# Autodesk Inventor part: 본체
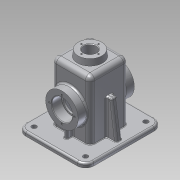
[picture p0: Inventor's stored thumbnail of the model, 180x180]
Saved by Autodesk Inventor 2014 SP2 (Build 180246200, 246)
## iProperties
Created: 2016-08
Part Number: 본체
Material: 알루미늄 6061
Document SubType Name: Modeling
Designer: user
Density: 2.71 g/cm^3
Appearance: 알루미늄 - 평지
Mass: 799.652 g
Surface Area: 913.3 cm^2
Volume: 295.075 cm^3
Author: user
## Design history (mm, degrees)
sketch "스케치2"
  geometry: L1 (52.5, -60)-(-52.5, -60); L2 (-52.5, -60)-(-52.5, 60); L3 (-52.5, 60)-(52.5, 60); L4 (52.5, 60)-(52.5, -60); L5 (52.5, -60)-(-52.5, 60); L6 (-52.5, -60)-(52.5, 60); 1 further point
  constraints: 12 end point, 2 midpoint, 2 parallel, 1 horizontal, 1 perpendicular
  dimensions: "d0" = 105 distance of L2.end L3.end; "d1" = 120 distance of L1.end L2.end
extrude "돌출1" new body sketch "스케치2" distance "d2" = 3; taper "d3" = 0 deg
sketch "스케치3"
  geometry: L1 (57.5, -65)-(-57.5, -65); L2 (-57.5, -65)-(-57.5, 65); L3 (-57.5, 65)-(57.5, 65); L4 (57.5, 65)-(57.5, -65); L5 (57.5, -65)-(-57.5, 65); L6 (-57.5, -65)-(57.5, 65); 1 further point
  constraints: 12 end point, 2 midpoint, 2 parallel, 1 horizontal, 1 perpendicular
  dimensions: "d4" = 115 distance of L2.end L3.end; "d5" = 130 distance of L1.end L2.end
extrude "돌출2" join sketch "스케치3" distance "d6" = 7; taper "d7" = 0 deg
sketch "스케치4"
  geometry: L1 (-32.5, -32.5)-(32.5, -32.5); L2 (32.5, -32.5)-(32.5, 32.5); L3 (32.5, 32.5)-(-32.5, 32.5); L4 (-32.5, 32.5)-(-32.5, -32.5); L5 (-32.5, -32.5)-(32.5, 32.5); L6 (32.5, -32.5)-(-32.5, 32.5); 1 further point
  constraints: 12 end point, 2 midpoint, 2 parallel, 1 horizontal, 1 perpendicular
  dimensions: "d8" = 65 distance of L3.end L2.end; "d9" = 65 distance of L2.end L1.end
extrude "돌출3" join sketch "스케치4" distance "d10" = 100; taper "d11" = 0 deg
sketch "스케치5"
  geometry: L1 (32.5, -32.5)-(-32.5, -32.5) reference; L2 (-32.5, -32.5)-(-32.5, 32.5) reference; L3 (-32.5, 32.5)-(32.5, 32.5) reference; L4 (32.5, 32.5)-(32.5, -32.5) reference; L5 (27.5, 27.5)-(-27.5, 27.5); L6 (-27.5, 27.5)-(-27.5, -27.5); L7 (-27.5, -27.5)-(27.5, -27.5); L8 (27.5, -27.5)-(27.5, 27.5); 1 further point
  constraints: 8 end point, 3 other
  dimensions: "d12" = 5 distance between parallel lines of L3 L5
extrude "돌출4" cut sketch "스케치5" distance "d13" = 105; taper "d14" = 0 deg
sketch "스케치6"
  geometry: C1 r 27.5 at (32.5, 45); 1 further point
  constraints: 1 centre point, 1 vertical alignment
  dimensions: "d15" = 55 diameter of C1; "d16" = 55 distance of point (32.5, -10) C1.centre
extrude "돌출5" join sketch "스케치6" distance "d17" = 15; taper "d18" = 0 deg
fillet "모깎기1" dims "d19" = 8
fillet "모깎기2" dims "d20" = 8
fillet "모깎기3" dims "d21" = 3
sketch "스케치9"
  geometry: L1 (-57.5, -65)-(-57.5, 65) reference; L2 (-32.5, 24.5)-(-32.5, -24.5) reference; L3 (-49.5, 5)-(-49.5, -5); L4 (-49.5, -5)-(-32.5, -5); L5 (-49.5, 5)-(-32.5, 5); L6 (-32.5, 5)-(-32.5, -5); 2 further points
  constraints: 8 end point, 2 perpendicular, 2 point on line, 1 collinear, 1 horizontal alignment, 1 midpoint, 1 parallel
  dimensions: "d36" = 10 distance of L3.start L3.end; "d37" = 8 distance between parallel lines of L1 L3
extrude "돌출7" join sketch "스케치9" distance "d38" = 60; taper "d39" = 0 deg
feature "면 기울기1" dims angle "d40" = 8 deg
sketch "스케치10"
  geometry: L1 (24.5, -32.5)-(-24.5, -32.5) reference; L2 (-3, -42.5)-(3, -42.5); L3 (-24.5, -27.5)-(24.5, -27.5) reference; L4 (3, -42.5)-(3, -27.5); L5 (-3, -42.5)-(-3, -27.5); L6 (-3, -27.5)-(3, -27.5); 2 further points
  constraints: 8 end point, 2 perpendicular, 2 point on line, 1 collinear, 1 midpoint, 1 parallel, 1 vertical alignment
  dimensions: "d41" = 15 distance of L2.end L4.end; "d42" = 6 distance of L2.start L2.end
extrude "돌출8" join sketch "스케치10" stored distance "d43" = 70; taper "d44" = 0 deg
sketch "스케치11"
  geometry: L1 (18.772, -65)-(-18.772, -65) reference; L2 (32.5, -47)-(32.5, 45) reference; 2 further points
  constraints: 1 other
  dimensions: "d45" = 26 distance from line of L1 point (0, -39); "d46" = 32.5 distance from line of L2 point (0, -39)
feature "엠보싱1" sketch "스케치11" dims "d8" = 65, "d9" = 65, "d47" = 0.5, "d48" = 0
hole "구멍1" diameter "d51" = 35; stored, may be unused: countersink angle "d55" = 90 deg, drill point angle "d57" = 0 deg; dims "d49" = 10, "d50" = 10, "d52" = 6, "d53" = 4, "d54" = 2, "d56" = 17
hole "구멍2" diameter "d60" = 35; stored, may be unused: countersink angle "d64" = 90 deg, drill point angle "d66" = 0 deg; dims "d58" = 10, "d59" = 10, "d61" = 6, "d62" = 4, "d63" = 2, "d65" = 17
hole "구멍3" diameter "d69" = 30; stored, may be unused: countersink angle "d73" = 90 deg, drill point angle "d75" = 0 deg; dims "d67" = 10, "d68" = 10, "d70" = 6, "d71" = 4, "d72" = 2, "d74" = 3
hole "구멍4" diameter "d78" = 30; stored, may be unused: countersink angle "d82" = 90 deg, drill point angle "d84" = 0 deg; dims "d76" = 10, "d77" = 10, "d79" = 6, "d80" = 4, "d81" = 2, "d83" = 3
fillet "모깎기4" dims "d85" = 14
fillet "모깎기5" dims "d86" = 9
hole "구멍5" diameter "d89" = 8; stored, may be unused: countersink angle "d93" = 90 deg, drill point angle "d95" = 0 deg; dims "d87" = 10, "d88" = 10, "d90" = 6, "d91" = 4, "d92" = 2, "d94" = 3
hole "구멍6" diameter "d98" = 8; stored, may be unused: countersink angle "d102" = 90 deg, drill point angle "d104" = 0 deg; dims "d96" = 10, "d97" = 10, "d99" = 6, "d100" = 4, "d101" = 2, "d103" = 3
hole "구멍7" diameter "d107" = 8; stored, may be unused: countersink angle "d111" = 90 deg, drill point angle "d113" = 0 deg; dims "d105" = 10, "d106" = 10, "d108" = 6, "d109" = 4, "d110" = 2, "d112" = 3
hole "구멍8" diameter "d116" = 8; stored, may be unused: countersink angle "d120" = 90 deg, drill point angle "d122" = 0 deg; dims "d114" = 10, "d115" = 10, "d117" = 6, "d118" = 4, "d119" = 2, "d121" = 3
fillet "모깎기6" dims "d123" = 3
fillet "모깎기7" dims "d124" = 3
fillet "모깎기8" dims "d125" = 1
chamfer "모따기1" distance "d135" = 1; stored, may be unused: second distance "d136" = 2, angle "d137" = 45 deg
sketch "스케치12" dims "d138" = 42
  geometry: 3 further points
  constraints: 3 vertical alignment, 2 other
  dimensions: "d139" = 55 distance of point (0, -55) point (0, 0)
hole "구멍10" sketch "스케치12" at (0, 21) diameter "d140" = 3.242; stored, may be unused: countersink angle "d144" = 90 deg, drill point angle "d146" = 118 deg; dims "d141" = 8, "d142" = 4, "d143" = 2, "d145" = 10
fillet "모깎기9" dims "d161" = 0.3
node "작업 평면1"
sketch "스케치14"
  geometry: C1 r 20 at (0, 0); 1 further point
  constraints: 1 centre point, 1 coincident
  dimensions: "d163" = 40 diameter of C1
extrude "돌출9" join sketch "스케치14" stored distance "d164" = 70; taper "d165" = 7 deg
hole "구멍12" diameter "d168" = 21; stored, may be unused: countersink angle "d172" = 90 deg, drill point angle "d174" = 0 deg; dims "d166" = 10, "d167" = 10, "d169" = 7, "d170" = 4, "d171" = 2, "d173" = 9
chamfer "모따기2" distance "d175" = 1; stored, may be unused: second distance "d176" = 2, angle "d177" = 45 deg
sketch "스케치15" dims "d178" = 29
  geometry: 3 further points
  constraints: 2 vertical alignment, 1 coincident, 2 other
hole "구멍13" sketch "스케치15" at (0, -14.5) diameter "d179" = 2.459; stored, may be unused: countersink angle "d183" = 90 deg, drill point angle "d185" = 118 deg; dims "d180" = 7, "d181" = 4, "d182" = 2, "d184" = 9
node "솔리드1"
mirror "대칭1"
mirror "대칭2"
mirror "대칭3"
pattern_circular "원형 패턴1" dims angle "d148" = 360 deg
mirror "대칭4"
pattern_circular "원형 패턴3" dims angle "d187" = 360 deg
node "투영된 루프1"
